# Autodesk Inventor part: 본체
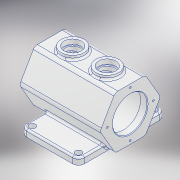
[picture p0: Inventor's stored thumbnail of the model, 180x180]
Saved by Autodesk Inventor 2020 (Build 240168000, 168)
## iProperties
Created: 2021-06
Part Number: 본체
Material: 알루미늄 6061
Document SubType Name: Modeling
Designer: 605-3
Density: 2.7 g/cm^3
Appearance: 알루미늄 - 평지
Mass: 1495.28 g
Surface Area: 1102.36 cm^2
Volume: 553.806 cm^3
Author: 605-3
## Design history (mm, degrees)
sketch "스케치1" dims "d0" = 105
  geometry: L1 (45.466, -26.25)-(0, -52.5); L2 (0, -52.5)-(-45.466, -26.25); L3 (-45.466, -26.25)-(-45.466, 26.25); L4 (-45.466, 26.25)-(0, 52.5); L5 (0, 52.5)-(45.466, 26.25); L6 (45.466, 26.25)-(45.466, -26.25); 3 further points
  constraints: 12 end point, 2 coincident, 1 vertical, 16 other
extrude "돌출1" new body sketch "스케치1" stored distance "d1" = 140; taper "d2" = 0 deg
node "작업 평면3"
sketch "스케치2"
  geometry: L1 (45, -75)-(-55, -75); L2 (-55, -75)-(-55, 75); L3 (-55, 75)-(45, 75); L4 (45, 75)-(45, -75); L5 (70, -26.25)-(70, -52.5) reference; L6 (-70, -52.5)-(-70, -26.25) reference; 1 further point
  constraints: 8 end point, 2 parallel, 1 horizontal, 1 perpendicular
  dimensions: "d4" = 25 distance between parallel lines of L4 L5; "d5" = 15 distance between parallel lines of L2 L6; "d6" = 150 distance of L3.end L1.start; "d7" = 75 distance from line of point (0, 0) L1
extrude "돌출2" join sketch "스케치2" distance "d8" = 12; taper "d9" = 0 deg
sketch "스케치3"
  geometry: C1 r 30 at (0, 0); 1 further point
  constraints: 1 centre point, 1 coincident
  dimensions: "d10" = 60 diameter of C1
extrude "돌출3" cut sketch "스케치3" distance "d11" = 12; taper "d12" = 0 deg
sketch "스케치4"
  geometry: C1 r 37.5 at (0, 0); 1 further point
  constraints: 1 centre point, 1 coincident
  dimensions: "d13" = 75 diameter of C1
extrude "돌출4" cut sketch "스케치4" distance "d14" = 116; taper "d15" = 0 deg
sketch "스케치5"
  geometry: C1 r 30 at (0, 0); 1 further point
  constraints: 1 centre point, 1 coincident
  dimensions: "d16" = 60 diameter of C1
extrude "돌출5" cut sketch "스케치5" distance "d17" = 12; taper "d18" = 0 deg
node "작업 평면5"
sketch "스케치7"
  geometry: L1 (70, -26.25)-(70, -52.5) reference; C1 r 20 at (30, 0); C2 r 20 at (-30, 0); 1 further point
  constraints: 2 centre point, 2 horizontal alignment
  dimensions: "d24" = 40 diameter of C1; "d25" = 40 diameter of C2; "d26" = 40 distance from line of C1.centre L1; "d27" = 60 distance of C2.centre C1.centre
extrude "돌출6" join sketch "스케치7" stored distance "d28" = 12; taper "d29" = 0 deg
sketch "스케치8"
  geometry: C1 r 20 at (0, 0) reference; C2 r 20 at (60, 0) reference; 3 further points
  constraints: 2 coincident
hole "구멍1" sketch "스케치8" at (0, 0), (60, 0) diameter "d30" = 25; stored, may be unused: countersink angle "d34" = 90 deg, drill point angle "d36" = 0 deg; dims "d31" = 6, "d32" = 30, "d33" = 8, "d35" = 32.25
fillet "모깎기1" dims "d37" = 10
sketch "스케치9"
  geometry: A1 r 10 centre (-35, -65) between (-45, -65) and (-35, -75) reference; A2 r 10 centre (45, -65) between (45, -75) and (55, -65) reference; A3 r 10 centre (45, 65) between (55, 65) and (45, 75) reference; A4 r 10 centre (-35, 65) between (-35, 75) and (-45, 65) reference; 5 further points
  constraints: 4 coincident
hole "구멍2" sketch "스케치9" at (-35, -65), (45, -65), (45, 65), (-35, 65) diameter "d38" = 11; stored, may be unused: countersink angle "d42" = 90 deg, drill point angle "d44" = 0 deg; dims "d39" = 6, "d40" = 30, "d41" = 8, "d43" = 32.25
sketch "스케치10" dims "d45" = 80
  geometry: 3 further points
  constraints: 2 vertical alignment, 1 coincident, 2 other
hole "구멍3" sketch "스케치10" at (0, 40) diameter "d46" = 3.242; stored, may be unused: countersink angle "d50" = 90 deg, drill point angle "d52" = 120 deg; dims "d47" = 8, "d48" = 30, "d49" = 8, "d51" = 10
sketch "스케치11"
  geometry: L1 (0, 0)-(-40, 0); L2 (0, 0)-(-28.284, 28.284); A1 r 40 centre (0, 0) between (-40, 0) and (-28.284, 28.284); 2 further points
  constraints: 4 end point, 2 coincident, 2 point on circle, 1 centre point, 1 horizontal
  dimensions: "d56" = 80 diameter of A1; "d58" = 45 deg angle of L2 L1
hole "구멍4" sketch "스케치11" at (-28.284, 28.284) diameter "d59" = 3.242; stored, may be unused: countersink angle "d63" = 90 deg, drill point angle "d65" = 120 deg; dims "d60" = 8, "d61" = 30, "d62" = 8, "d64" = 10
fillet "모깎기2" dims "d69" = 8
fillet "모깎기3" dims "d70" = 3
fillet "모깎기4" dims "d71" = 3
fillet "모깎기5" dims "d72" = 3
sketch "스케치12"
  geometry: L1 (-35, 72)-(45, 72) reference; L2 (45, 75)-(-35, 75) reference; L3 (-45, 65)-(-45, 32.293) reference; 2 further points
  constraints: 1 other
  dimensions: "d73" = 14 distance from line of point (5, 61) L2; "d74" = 50 distance from line of point (5, 61) L3
feature "엠보싱1" sketch "스케치12" dims "d75" = 0.5, "d76" = 0
fillet "모깎기6" dims "d77" = 5
chamfer "모따기1" distance "d78" = 1; stored, may be unused: second distance "d79" = 2, angle "d80" = 45 deg
node "솔리드1"
pattern_circular "원형 패턴1" dims angle "d54" = 360 deg
pattern_circular "원형 패턴2" dims angle "d67" = 360 deg
feature "A9D066F2-1C7D-4E18-AEED-F7BC21143FA4" dims "d38" = 11, "d39" = 6, "d40" = 30, "d41" = 8, "d42" = 90 deg, "d43" = 32.25, "d44" = 0
other parameters: "d23" = 52.5
